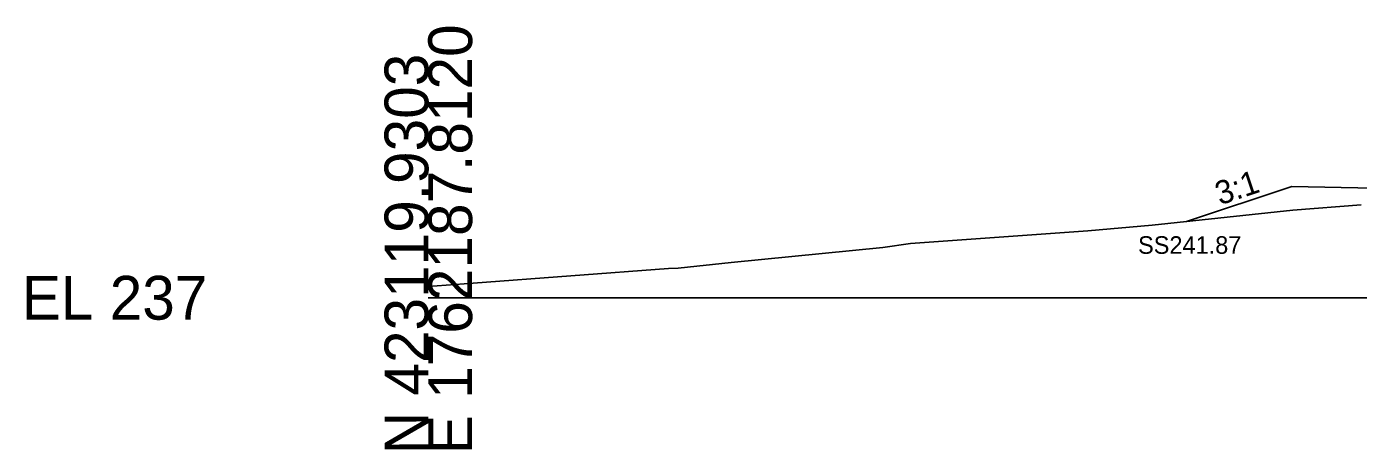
# Model space of a CAD drawing. Extents: x -26 to 3203, y -11010 to 4024.
# Drawn here: x -25.7 to 59.5, y -1009.7 to -982.7 of the extents above; entities that cross this region are included whole.
import ezdxf

# ---------------------------------------------------------------- set-up
doc = ezdxf.new("R2010")
doc.units = 0
for name, color, linetype in [('Default', 7, 'Continuous'), ('Exist Cross Section Cell', 7, 'Continuous'), ('Exist XS Ground Line', 7, 'Continuous'), ('Prop CMT Slope Grass', 7, 'Continuous'), ('Prop XS Side Slope Text', 7, 'Continuous'), ('Prop XS SS Elevation Text', 7, 'Continuous'), ('Scratch_Level_0', 7, 'Continuous')]:
    doc.layers.add(name, color=color, linetype=linetype)

msp = doc.modelspace()

# ---------------------------------------------------------------- linework, layer by layer
at = {"layer": 'Exist Cross Section Cell'}
msp.add_line((0, -1000), (100, -1000), dxfattribs=at)
at = {"layer": 'Exist XS Ground Line'}
msp.add_lwpolyline([(0, -999.278), (2.868, -999.067), (15.363, -998.131), (15.974, -998.1), (19.36, -997.736), (29.08, -996.778), (30.833, -996.539), (42.186, -995.709), (46.304, -995.363), (55.292, -994.389), (59.658, -994.06)], dxfattribs=at)
msp.add_lwpolyline([(0, -999.278), (2.868, -999.067), (15.363, -998.131), (15.974, -998.1), (19.36, -997.736), (29.08, -996.778), (30.833, -996.539), (42.186, -995.709), (46.304, -995.363), (55.292, -994.389), (59.658, -994.06)], dxfattribs=at)
msp.add_lwpolyline([(0, -999.278), (2.868, -999.067), (15.363, -998.131), (15.974, -998.1), (19.36, -997.736), (29.08, -996.778), (30.833, -996.539), (42.186, -995.709), (46.304, -995.363), (55.292, -994.389), (59.658, -994.06)], dxfattribs=at)
msp.add_lwpolyline([(0, -999.278), (2.868, -999.067), (15.363, -998.131), (15.974, -998.1), (19.36, -997.736), (29.08, -996.778), (30.833, -996.539), (42.186, -995.709), (46.304, -995.363), (55.292, -994.389), (59.658, -994.06)], dxfattribs=at)
msp.add_lwpolyline([(0, -999.278), (2.868, -999.067), (15.363, -998.131), (15.974, -998.1), (19.36, -997.736), (29.08, -996.778), (30.833, -996.539), (42.186, -995.709), (46.304, -995.363), (55.292, -994.389), (59.658, -994.06)], dxfattribs=at)
at = {"layer": 'Prop CMT Slope Grass'}
msp.add_lwpolyline([(64.72, -993.072), (55.22, -992.882), (48.486, -995.126)], dxfattribs=at)

# ---------------------------------------------------------------- texts
at = {"layer": 'Default'}
msp.add_text('-', height=0.0001, dxfattribs=at).set_placement((0, -1000))
at = {"layer": 'Exist Cross Section Cell'}
for s, p in [('E 1762187.8120', (2.8, -1010)), ('N 423119.9303', (0, -1010))]:
    msp.add_text(s, height=2.8, rotation=90, dxfattribs=at).set_placement(p)
msp.add_text('EL 237', height=2.8, dxfattribs=at).set_placement((-26, -1001.4))
at = {"layer": 'Prop XS Side Slope Text'}
msp.add_text('3:1', height=1.5, rotation=18.43493, dxfattribs=at).set_placement((50.63, -994.095))
at = {"layer": 'Prop XS SS Elevation Text'}
msp.add_text('SS241.87', height=1.125, dxfattribs=at).set_placement((45.394, -997.189))
at = {"layer": 'Scratch_Level_0'}
for s, p in [('LT_CSLP_Pnt', (55.122, -992.892)), ('Exterior Boundary', (48.327, -995.136)), ('LT_Slope_Fill', (48.392, -995.136))]:
    msp.add_text(s, height=0.02, dxfattribs=at).set_placement(p)

doc.saveas('drawing.dxf')
